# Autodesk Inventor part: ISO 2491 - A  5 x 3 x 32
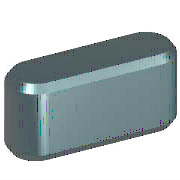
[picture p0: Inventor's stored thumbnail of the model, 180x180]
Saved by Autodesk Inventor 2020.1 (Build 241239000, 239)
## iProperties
Created: 2019-01
Part Number: ISO 2491 - A  5 x 3 x 32
Material: Stahl, weich
Description: Passfedern
Document SubType Name: Modeling
Standard: ISO 2491
Designer: lutzd
Standard Revision: First edition 1974-08-15
Standards Organization: ISO
Language: de-DE
Size Designation: A  5 x 3 x 32
Categories: <MemberInstance><Categories><Category DisplayName="Wellenteile" InternalName="7f7aeb1f-a693-4053-b835-cee3144e0d98" Mnemonic="SHFT"><Category DisplayName="Passf
Mass: 3.55515 g
Surface Area: 4.8531 cm^2
Volume: 0.452886 cm^3
Density: 7.85 g/cm^3
Appearance: Halbpoliert
IsCustomPart: 0
Author: lutzd
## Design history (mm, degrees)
workplane "Work Plane1"
workplane "Work Plane2"
sketch "Skizze1"
  geometry: L1 (2.5, 2.5)-(29.5, 2.5); L2 (29.5, -2.5)-(2.5, -2.5); L3 (0, 9.4)-(0, -7.4) reference; L4 (-5, 0)-(30, 0) reference; L5 (32, 0)-(32, 7); A1 r 2.5 centre (2.5, 0) between (2.5, 2.5) and (2.5, -2.5); A2 r 2.5 centre (29.5, 0) between (29.5, -2.5) and (29.5, 2.5)
  constraints: 6 end point, 5 point on circle, 4 tangent, 3 point on line, 2 centre point, 1 horizontal, 1 parallel, 1 perpendicular
  dimensions: "d0" = 2.5 radius of A1 (= 0.5 x PB); "d13" = 2.5 radius of A2 (= 0.5 x PB); "d14" = 32 distance between parallel lines of L5 L3 (= NLG)
extrude "Körper1" new body sketch "Skizze1" taper "d3" = 0 deg; stored distance "d4" = 10
workplane "Work Plane3"
body "Solid1"
chamfer "Fase1" distance "d8" = 0.4 (= PHH); stored, may be unused: second distance "d9" = 0.4 (= PHH), angle "d15" = 45 deg
other parameters: "d1" = -1.8 (= -PNT), "d2" = 1.2 (= PH - PNT), "NLG" = 32 [user parameter; used in 1 equation term], "PB" = 5 [user parameter; used in 2 equation terms], "PNT" = 1.8 [user parameter; used in 2 equation terms], "PH" = 3 [user parameter; used in 1 equation term], "PHH" = 0.4 [user parameter; used in 2 equation terms], "d10" = 0, "d16" = 0, "d17" = 0, "d18" = 0, "RR" = 0.16 [user parameter], "WDMIN" = 12 [user parameter], "WDMAX" = 17 [user parameter], "PLB1" = 32 [user parameter], "PLB2" = 32 [user parameter], "PUEB" = 1.4 [user parameter]
